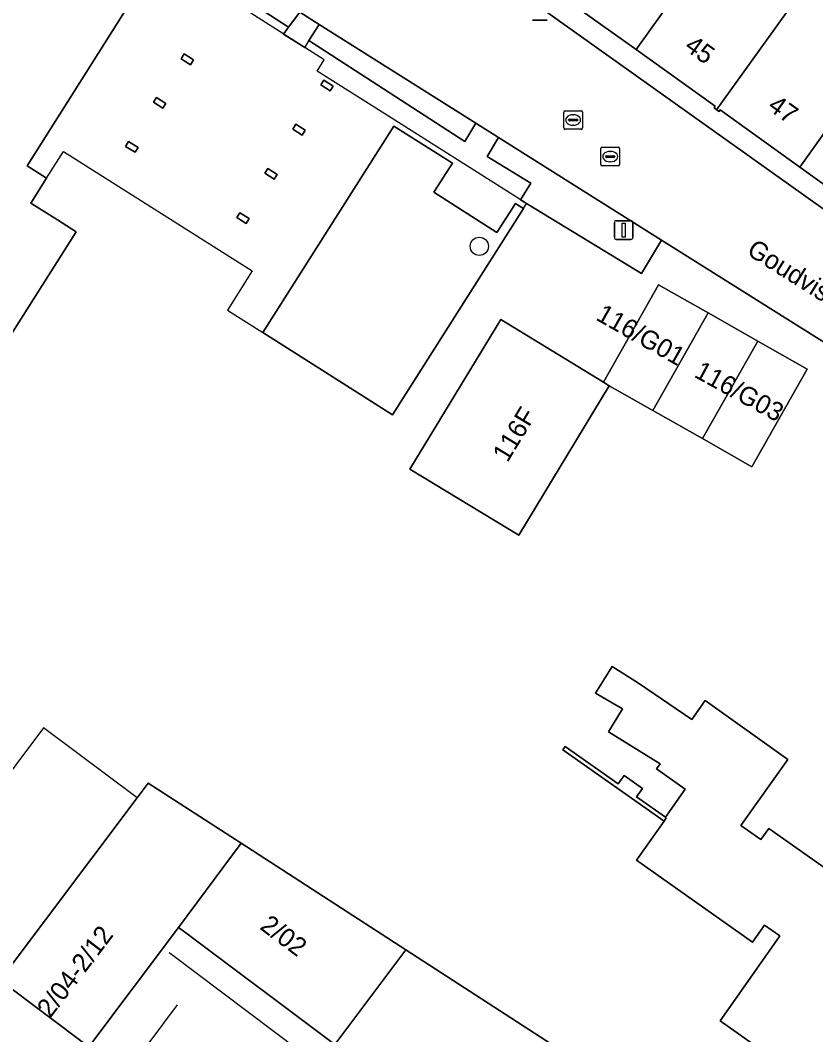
# Model space of a CAD drawing. Extents: x 160102 to 160934, y 382045 to 382923.
# Drawn here: x 160653.7 to 160696.3, y 382504.7 to 382559 of the extents above; entities that cross this region are included whole.
import ezdxf

# ---------------------------------------------------------------- set-up
doc = ezdxf.new("R2010")
doc.units = 0
for name, color, linetype in [('IMGEO_Boom', 7, 'Continuous'), ('IMGEO_Erf', 7, 'Continuous'), ('IMGEO_Groenvoorziening', 7, 'Continuous'), ('IMGEO_Kolk', 7, 'Continuous'), ('IMGEO_Lichtmast', 7, 'Continuous'), ('IMGEO_Lijnafwatering', 7, 'Continuous'), ('IMGEO_Muur', 7, 'Continuous'), ('IMGEO_Openbare_ruimte_label', 7, 'Continuous'), ('IMGEO_Pand', 7, 'Continuous'), ('IMGEO_Pand_nummerreeks', 7, 'Continuous'), ('IMGEO_Pand_overbouw', 7, 'Continuous'), ('IMGEO_Rijbaan_lokaal_open', 7, 'Continuous'), ('IMGEO_Rioolput', 7, 'Continuous'), ('IMGEO_Voetpad_open', 7, 'Continuous')]:
    doc.layers.add(name, color=color, linetype=linetype)

msp = doc.modelspace()

# ---------------------------------------------------------------- linework, layer by layer
at = {"layer": 'IMGEO_Boom'}
msp.add_circle((160678.287, 382546.928), 0.489, dxfattribs=at)
at = {"layer": 'IMGEO_Erf'}
for points in [[(160652.564, 382567.156), (160660.609, 382562.063), (160660.792, 382561.947), (160654.021, 382551.249), (160655.069, 382550.586), (160654.22, 382549.244), (160655.648, 382548.34), (160656.657, 382547.701), (160653.009, 382541.939)], [(160700.091, 382539.706), (160688.062, 382547.254), (160686.993, 382545.476), (160680.502, 382549.41), (160681.055, 382550.307), (160678.713, 382551.746), (160679.323, 382552.761), (160678.105, 382553.529), (160677.508, 382552.549), (160669.148, 382557.955), (160668.921, 382557.583), (160667.78, 382558.309), (160668.051, 382558.669), (160661.29, 382563.07)], [(160699.724, 382548.14), (160695.488, 382551.176), (160691.218, 382554.237), (160691.154, 382554.148), (160691.018, 382554.245), (160690.882, 382554.343), (160690.946, 382554.432), (160686.698, 382557.476), (160682.45, 382560.521)], [(160681.405, 382559.84), (160696.857, 382548.846)], [(160694.517, 382503.064), (160691.205, 382505.394), (160694.218, 382509.675), (160694.413, 382509.952), (160693.584, 382510.536), (160692.943, 382509.625), (160686.721, 382514.004), (160688.204, 382516.11), (160682.776, 382519.93), (160682.897, 382520.102), (160685.745, 382518.098), (160686.061, 382518.548), (160687.042, 382517.857), (160686.726, 382517.407), (160688.28, 382516.313), (160689.338, 382517.816), (160687.798, 382518.915), (160687.989, 382519.183), (160685.212, 382520.895), (160685.967, 382522.119), (160684.515, 382522.961), (160685.423, 382524.394), (160686.823, 382523.508), (160689.686, 382521.559), (160690.416, 382522.582), (160694.849, 382519.416), (160692.319, 382515.873), (160693.398, 382515.113), (160693.823, 382515.708), (160702.303, 382509.735)]]:
    msp.add_lwpolyline(points, dxfattribs=at)
for points in [[(160662.282, 382556.985), (160662.443, 382557.239), (160662.95, 382556.918), (160662.789, 382556.664)], [(160669.787, 382555.584), (160669.949, 382555.837), (160670.454, 382555.514), (160670.293, 382555.261)], [(160660.803, 382554.648), (160660.964, 382554.901), (160661.47, 382554.58), (160661.31, 382554.327)], [(160668.283, 382553.214), (160668.444, 382553.467), (160668.95, 382553.145), (160668.789, 382552.891)], [(160666.677, 382542.299), (160673.705, 382553.372), (160676.844, 382551.379), (160675.853, 382549.825), (160679.233, 382547.671), (160680.234, 382549.228), (160680.346, 382549.157), (160680.662, 382548.957), (160673.621, 382537.891)], [(160659.307, 382552.284), (160659.468, 382552.538), (160659.977, 382552.221), (160659.816, 382551.967)], [(160666.777, 382550.84), (160666.937, 382551.096), (160667.444, 382550.777), (160667.285, 382550.522)], [(160665.275, 382548.475), (160665.434, 382548.729), (160665.943, 382548.41), (160665.783, 382548.156)], [(160690.256, 382536.615), (160687.598, 382538.124), (160685.263, 382539.449), (160680.404, 382531.434), (160674.56, 382534.976), (160679.437, 382543.01), (160684.945, 382539.643), (160687.909, 382544.866), (160690.568, 382543.357), (160693.226, 382541.848), (160695.885, 382540.34), (160692.915, 382535.107)], [(160665.515, 382514.919), (160674.342, 382509.208), (160692.58, 382497.408), (160687.754, 382491.078), (160677.802, 382498.666), (160670.528, 382504.122), (160662.61, 382510.061), (160662.14, 382510.411), (160657.342, 382504.002), (160650.301, 382494.596), (160643.343, 382485.301), (160633.336, 382491.531), (160637.422, 382496.967), (160642.026, 382493.523), (160645.524, 382498.178), (160652.582, 382507.572), (160659.926, 382517.347), (160660.526, 382518.146)]]:
    msp.add_lwpolyline(points, close=True, dxfattribs=at)
at = {"layer": 'IMGEO_Groenvoorziening'}
msp.add_lwpolyline([(160650.804, 382568.283), (160644.14, 382557.763), (160644.821, 382557.292), (160652.176, 382568.858), (160661.29, 382563.07), (160668.051, 382558.669), (160668.663, 382559.479), (160653.583, 382568.983)], dxfattribs=at)
for points in [[(160669.701, 382558.825), (160669.148, 382557.955), (160677.508, 382552.549), (160678.105, 382553.529)], [(160679.323, 382552.761), (160678.713, 382551.746), (160681.055, 382550.307), (160680.502, 382549.41), (160686.993, 382545.476), (160688.062, 382547.254)]]:
    msp.add_lwpolyline(points, close=True, dxfattribs=at)
at = {"layer": 'IMGEO_Kolk'}
for p, q in [((160684.812, 382551.312), (160684.812, 382552.164)), ((160684.887, 382552.238), (160685.739, 382552.238)), ((160685.3, 382552.018), (160685.325, 382552.018)), ((160685.813, 382552.164), (160685.813, 382551.312)), ((160685.071, 382551.732), (160685.071, 382551.744)), ((160685.509, 382551.695), (160685.111, 382551.695)), ((160685.114, 382551.781), (160685.512, 382551.781)), ((160685.323, 382551.458), (160685.298, 382551.458)), ((160685.555, 382551.744), (160685.555, 382551.732)), ((160685.739, 382551.238), (160684.887, 382551.238))]:
    msp.add_line(p, q, dxfattribs=at)
for points in [[(160684.812, 382551.312), (160684.812, 382552.164)], [(160684.887, 382552.238), (160685.739, 382552.238)], [(160685.813, 382552.164), (160685.813, 382551.312)], [(160685.739, 382551.238), (160684.887, 382551.238)]]:
    msp.add_lwpolyline(points, dxfattribs=at)
for centre, radius, start, end in [((160684.889, 382552.162), 0.0765, 91.552, 178.448), ((160684.889, 382552.162), 0.0765, 91.552, 178.448), ((160685.737, 382552.162), 0.0765, 1.552, 88.448), ((160685.737, 382552.162), 0.0765, 1.552, 88.448), ((160684.889, 382551.314), 0.0765, 181.552, 268.448), ((160684.889, 382551.314), 0.0765, 181.552, 268.448), ((160685.111, 382551.741), 0.0403, 85.8775, 175.7526), ((160685.108, 382551.731), 0.0366, 178.938, 274.7102), ((160685.512, 382551.738), 0.043, 264.8664, 352.4533), ((160685.516, 382551.743), 0.0386, 1.7309, 96.639), ((160685.737, 382551.314), 0.0765, 271.552, 358.448), ((160685.737, 382551.314), 0.0765, 271.552, 358.448)]:
    msp.add_arc(centre, radius, start, end, dxfattribs=at)
for centre, major_axis, ratio, start_param, end_param in [((160685.299, 382551.738), (-0.387, 0.002), 0.722429, 4.712389, 7.853982), ((160685.324, 382551.738), (-0.39, 0.002), 0.717154, 1.570796, 4.712389)]:
    msp.add_ellipse(centre, major_axis=major_axis, ratio=ratio, start_param=start_param, end_param=end_param, dxfattribs=at)
at = {"layer": 'IMGEO_Lichtmast'}
for p, q in [((160681.934, 382559.044), (160681.144, 382559.044)), ((160681.144, 382559.044), (160681.934, 382559.044)), ((160685.538, 382547.398), (160685.538, 382548.198)), ((160685.538, 382548.198), (160685.538, 382547.398)), ((160685.638, 382548.298), (160686.428, 382548.298)), ((160686.428, 382548.298), (160685.638, 382548.298)), ((160686.528, 382548.198), (160686.528, 382547.398)), ((160686.528, 382547.398), (160686.528, 382548.198)), ((160686.428, 382547.298), (160685.638, 382547.298)), ((160685.638, 382547.298), (160686.428, 382547.298))]:
    msp.add_line(p, q, dxfattribs=at)
msp.add_lwpolyline([(160685.958, 382548.173), (160686.108, 382548.173), (160686.108, 382547.423), (160685.958, 382547.423), (160685.958, 382548.173)], dxfattribs=at)
for centre, start, end in [((160685.638, 382548.198), 90, 180), ((160685.638, 382548.198), 90, 180), ((160686.428, 382548.198), 0, 90), ((160686.428, 382548.198), 360, 90), ((160685.638, 382547.398), 180, 270), ((160685.638, 382547.398), 180, 270), ((160686.428, 382547.398), 270, 0), ((160686.428, 382547.398), 270, 0)]:
    msp.add_arc(centre, 0.1, start, end, dxfattribs=at)
at = {"layer": 'IMGEO_Lijnafwatering'}
for points in [[(160680.837, 382494.606), (160661.775, 382508.947), (160661.648, 382509.042)], [(160654, 382495.426), (160662.091, 382506.254)]]:
    msp.add_lwpolyline(points, dxfattribs=at)
at = {"layer": 'IMGEO_Muur'}
msp.add_lwpolyline([(160686.061, 382518.548), (160685.745, 382518.098), (160682.897, 382520.102), (160682.776, 382519.93), (160688.204, 382516.11), (160688.323, 382516.284), (160688.28, 382516.313), (160686.726, 382517.407), (160687.042, 382517.857)], close=True, dxfattribs=at)
at = {"layer": 'IMGEO_Pand'}
for points in [[(160692.006, 382564.88), (160691.87, 382564.977), (160691.806, 382564.887), (160687.691, 382567.833), (160687.755, 382567.922), (160687.407, 382568.171), (160682.021, 382560.695), (160682.386, 382560.432), (160682.45, 382560.521), (160686.698, 382557.476)], [(160696.327, 382561.65), (160695.477, 382562.259), (160692.078, 382564.692), (160692.142, 382564.782), (160692.006, 382564.88), (160686.698, 382557.476), (160690.946, 382554.432), (160690.882, 382554.343), (160691.018, 382554.245)], [(160700.787, 382558.594), (160700.65, 382558.691), (160700.586, 382558.601), (160697.189, 382561.033), (160696.327, 382561.65), (160691.018, 382554.245), (160691.154, 382554.148), (160691.218, 382554.237), (160695.488, 382551.176)], [(160705.108, 382555.364), (160704.249, 382555.979), (160700.859, 382558.406), (160700.923, 382558.496), (160700.787, 382558.594), (160695.488, 382551.176), (160699.724, 382548.14), (160699.66, 382548.051), (160699.796, 382547.954)], [(160662.443, 382557.239), (160662.282, 382556.985), (160662.789, 382556.664), (160662.95, 382556.918)], [(160669.949, 382555.837), (160669.787, 382555.584), (160670.293, 382555.261), (160670.454, 382555.514)], [(160660.964, 382554.901), (160660.803, 382554.648), (160661.31, 382554.327), (160661.47, 382554.58)], [(160668.444, 382553.467), (160668.283, 382553.214), (160668.789, 382552.891), (160668.95, 382553.145)], [(160680.662, 382548.957), (160680.346, 382549.157), (160680.234, 382549.228), (160679.233, 382547.671), (160675.853, 382549.825), (160676.844, 382551.379), (160673.705, 382553.372), (160666.677, 382542.299), (160673.621, 382537.891)], [(160659.468, 382552.538), (160659.307, 382552.284), (160659.816, 382551.967), (160659.977, 382552.221)], [(160666.937, 382551.096), (160666.777, 382550.84), (160667.285, 382550.522), (160667.444, 382550.777)], [(160665.434, 382548.729), (160665.275, 382548.475), (160665.783, 382548.156), (160665.943, 382548.41)], [(160690.568, 382543.357), (160687.909, 382544.866), (160684.945, 382539.643), (160685.263, 382539.449), (160687.598, 382538.124)], [(160690.568, 382543.357), (160687.598, 382538.124), (160690.256, 382536.615), (160693.226, 382541.848)], [(160685.263, 382539.449), (160684.945, 382539.643), (160679.437, 382543.01), (160674.56, 382534.976), (160680.404, 382531.434)], [(160690.256, 382536.615), (160692.915, 382535.107), (160695.885, 382540.34), (160693.226, 382541.848)], [(160665.515, 382514.919), (160660.526, 382518.146), (160659.926, 382517.347), (160652.582, 382507.572), (160657.342, 382504.002), (160662.14, 382510.411)], [(160665.515, 382514.919), (160662.14, 382510.411), (160662.61, 382510.061), (160670.528, 382504.122), (160674.342, 382509.208)], [(160674.342, 382509.208), (160670.528, 382504.122), (160677.802, 382498.666), (160687.754, 382491.078), (160692.58, 382497.408)], [(160652.582, 382507.572), (160645.524, 382498.178), (160650.301, 382494.596), (160657.342, 382504.002)]]:
    msp.add_lwpolyline(points, close=True, dxfattribs=at)
for points in [[(160653.009, 382541.939), (160656.657, 382547.701), (160655.648, 382548.34), (160654.22, 382549.244), (160655.069, 382550.586), (160654.021, 382551.249), (160660.792, 382561.947), (160660.609, 382562.063), (160652.564, 382567.156)], [(160702.303, 382509.735), (160693.823, 382515.708), (160693.398, 382515.113), (160692.319, 382515.873), (160694.849, 382519.416), (160690.416, 382522.582), (160689.686, 382521.559), (160686.823, 382523.508), (160685.423, 382524.394), (160684.515, 382522.961), (160685.967, 382522.119), (160685.212, 382520.895), (160687.989, 382519.183), (160687.798, 382518.915), (160689.338, 382517.816), (160688.28, 382516.313), (160688.323, 382516.284), (160688.204, 382516.11), (160686.721, 382514.004), (160692.943, 382509.625), (160693.584, 382510.536), (160694.413, 382509.952), (160694.218, 382509.675), (160691.205, 382505.394), (160694.517, 382503.064)]]:
    msp.add_lwpolyline(points, dxfattribs=at)
at = {"layer": 'IMGEO_Pand_overbouw'}
msp.add_lwpolyline([(160652.564, 382567.156), (160660.792, 382561.947), (160654.021, 382551.249), (160655.069, 382550.586), (160655.968, 382552.005), (160666.098, 382545.606), (160664.767, 382543.51), (160666.677, 382542.299), (160673.705, 382553.372), (160676.844, 382551.379), (160675.853, 382549.825), (160679.233, 382547.671), (160680.234, 382549.228), (160680.662, 382548.957), (160680.826, 382549.214), (160672.872, 382554.247), (160669.588, 382556.325), (160669.963, 382556.921), (160652.335, 382568.128)], dxfattribs=at)
msp.add_lwpolyline([(160652.582, 382507.572), (160659.926, 382517.347), (160654.91, 382521.109), (160647.574, 382511.327)], close=True, dxfattribs=at)
at = {"layer": 'IMGEO_Rijbaan_lokaal_open'}
msp.add_lwpolyline([(160668.663, 382559.479), (160669.701, 382558.825), (160678.105, 382553.529), (160679.323, 382552.761), (160688.062, 382547.254), (160700.091, 382539.706), (160700.294, 382539.578), (160707.362, 382535.112), (160707.032, 382534.59), (160716.399, 382527.998), (160720.487, 382525.12), (160720.519, 382525.165), (160724.312, 382522.505), (160728.051, 382527.836), (160727.481, 382528.245), (160717.298, 382535.547), (160717.251, 382535.482), (160716.812, 382535.797), (160714.326, 382537.58), (160713.206, 382538.382), (160713.186, 382538.354), (160712.547, 382537.478), (160696.857, 382548.846), (160681.405, 382559.84)], dxfattribs=at)
at = {"layer": 'IMGEO_Rioolput'}
for p, q in [((160682.824, 382553.272), (160682.824, 382554.124)), ((160682.899, 382554.198), (160683.751, 382554.198)), ((160683.825, 382554.124), (160683.825, 382553.272)), ((160683.083, 382553.692), (160683.083, 382553.704)), ((160683.521, 382553.655), (160683.123, 382553.655)), ((160683.126, 382553.741), (160683.524, 382553.741)), ((160683.312, 382553.978), (160683.337, 382553.978)), ((160683.567, 382553.704), (160683.567, 382553.692)), ((160683.751, 382553.198), (160682.899, 382553.198)), ((160683.335, 382553.418), (160683.31, 382553.418))]:
    msp.add_line(p, q, dxfattribs=at)
for points in [[(160682.824, 382553.272), (160682.824, 382554.124)], [(160682.899, 382554.198), (160683.751, 382554.198)], [(160683.825, 382554.124), (160683.825, 382553.272)], [(160683.751, 382553.198), (160682.899, 382553.198)]]:
    msp.add_lwpolyline(points, dxfattribs=at)
for centre, radius, start, end in [((160682.901, 382554.122), 0.0765, 91.552, 178.448), ((160682.901, 382554.122), 0.0765, 91.552, 178.448), ((160683.749, 382554.122), 0.0765, 1.552, 88.448), ((160683.749, 382554.122), 0.0765, 1.552, 88.448), ((160683.123, 382553.701), 0.0403, 85.8775, 175.7526), ((160683.12, 382553.691), 0.0366, 178.938, 274.7102), ((160683.524, 382553.698), 0.043, 264.8664, 352.4533), ((160683.528, 382553.703), 0.0386, 1.7309, 96.639), ((160682.901, 382553.274), 0.0765, 181.552, 268.448), ((160682.901, 382553.274), 0.0765, 181.552, 268.448), ((160683.749, 382553.274), 0.0765, 271.552, 358.448), ((160683.749, 382553.274), 0.0765, 271.552, 358.448)]:
    msp.add_arc(centre, radius, start, end, dxfattribs=at)
for centre, major_axis, ratio, start_param, end_param in [((160683.311, 382553.698), (-0.387, 0.002), 0.722429, 4.712389, 7.853982), ((160683.336, 382553.698), (-0.39, 0.002), 0.717154, 1.570796, 4.712389)]:
    msp.add_ellipse(centre, major_axis=major_axis, ratio=ratio, start_param=start_param, end_param=end_param, dxfattribs=at)
at = {"layer": 'IMGEO_Voetpad_open'}
msp.add_lwpolyline([(160669.701, 382558.825), (160668.663, 382559.479), (160668.051, 382558.669), (160667.78, 382558.309), (160668.921, 382557.583), (160669.148, 382557.955)], close=True, dxfattribs=at)

# ---------------------------------------------------------------- texts
at = {"layer": 'IMGEO_Openbare_ruimte_label'}
msp.add_text('Goudvisstraat', height=1, rotation=327.8366, dxfattribs=at).set_placement((160692.582, 382546.522))
at = {"layer": 'IMGEO_Pand_nummerreeks'}
for s, rotation, p in [('45', 324.3735, (160689.236, 382557.502)), ('47', 324.362, (160693.706, 382554.299)), ('116/G01', 330.474, (160684.486, 382543.013)), ('116/G03', 331.2849, (160689.759, 382539.95)), ('116F', 58.7742, (160679.795, 382535.291)), ('2/02', 323.1158, (160666.458, 382510.355)), ('2/04-2/12', 52.5984, (160655.267, 382505.512))]:
    msp.add_text(s, height=1, rotation=rotation, dxfattribs=at).set_placement(p)

doc.saveas('drawing.dxf')
